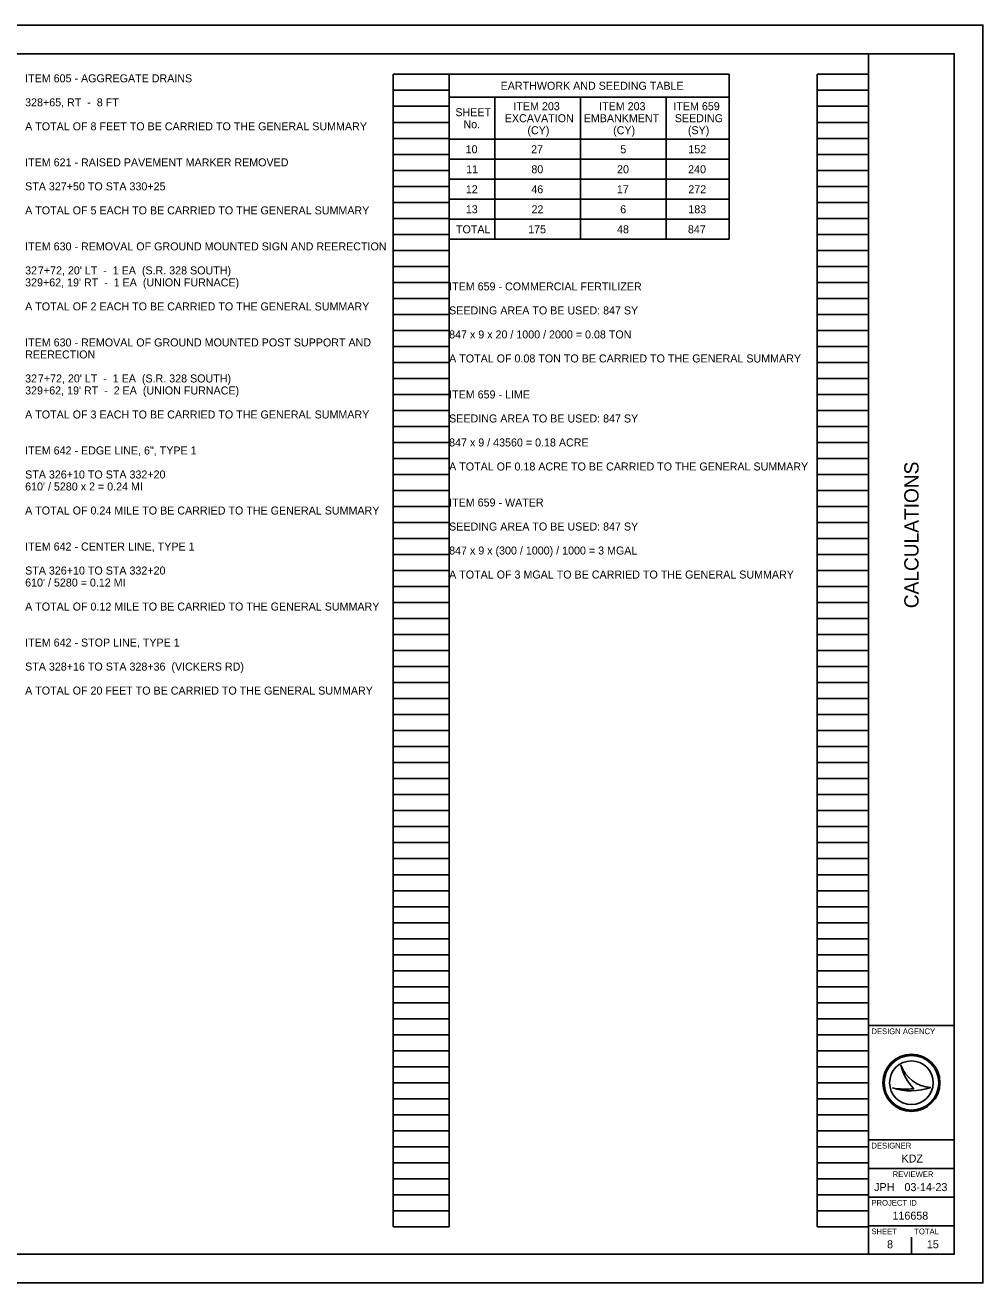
# Model space of a CAD drawing. Extents: x 0 to 34, y 0 to 22.
# Drawn here: x 17.24 to 34, y 0 to 22 of the extents above; entities that cross this region are included whole.
import ezdxf

# ---------------------------------------------------------------- set-up
doc = ezdxf.new("R2010")
doc.units = 0
for name, color, linetype in [('SH_Border', 7, 'Continuous'), ('SH_Cut_Line', 7, 'Continuous'), ('SH_Data', 7, 'Continuous'), ('SH_Text', 7, 'Continuous')]:
    doc.layers.add(name, color=color, linetype=linetype)

msp = doc.modelspace()

# ---------------------------------------------------------------- linework, layer by layer
at = {"layer": 'SH_Border'}
for p, q in [((32, 0.5), (32, 21.5)), ((32, 4.5), (33.5, 4.5)), ((32, 2.5), (33.5, 2.5)), ((32, 2), (33.5, 2)), ((32, 1.5), (33.5, 1.5)), ((32, 1), (33.5, 1))]:
    msp.add_line(p, q, dxfattribs=at)
msp.add_lwpolyline([(1.5, 21.5), (33.5, 21.5), (33.5, 0.5), (1.5, 0.5)], close=True, dxfattribs=at)
at = {"layer": 'SH_Cut_Line'}
msp.add_lwpolyline([(0, 0), (34, 0), (34, 22), (0, 22)], close=True, dxfattribs=at)
at = {"layer": 'SH_Data'}
for p, q in [((23.68, 0.98), (23.68, 21.14)), ((23.68, 21.14), (24.66, 21.14)), ((24.66, 0.98), (24.66, 21.14)), ((31.1, 0.98), (31.1, 21.14)), ((31.1, 21.14), (32, 21.14)), ((32, 0.98), (32, 21.14)), ((23.68, 20.86), (24.66, 20.86)), ((31.1, 20.86), (32, 20.86)), ((23.68, 20.58), (24.66, 20.58)), ((31.1, 20.58), (32, 20.58)), ((23.68, 20.3), (24.66, 20.3)), ((31.1, 20.3), (32, 20.3)), ((23.68, 20.02), (24.66, 20.02)), ((31.1, 20.02), (32, 20.02)), ((23.68, 19.74), (24.66, 19.74)), ((31.1, 19.74), (32, 19.74)), ((23.68, 19.46), (24.66, 19.46)), ((31.1, 19.46), (32, 19.46)), ((23.68, 19.18), (24.66, 19.18)), ((31.1, 19.18), (32, 19.18)), ((23.68, 18.9), (24.66, 18.9)), ((31.1, 18.9), (32, 18.9)), ((23.68, 18.62), (24.66, 18.62)), ((31.1, 18.62), (32, 18.62)), ((23.68, 18.34), (24.66, 18.34)), ((31.1, 18.34), (32, 18.34)), ((23.68, 18.06), (24.66, 18.06)), ((31.1, 18.06), (32, 18.06)), ((23.68, 17.78), (24.66, 17.78)), ((31.1, 17.78), (32, 17.78)), ((23.68, 17.5), (24.66, 17.5)), ((31.1, 17.5), (32, 17.5)), ((23.68, 17.22), (24.66, 17.22)), ((31.1, 17.22), (32, 17.22)), ((23.68, 16.94), (24.66, 16.94)), ((31.1, 16.94), (32, 16.94)), ((23.68, 16.66), (24.66, 16.66)), ((31.1, 16.66), (32, 16.66)), ((23.68, 16.38), (24.66, 16.38)), ((31.1, 16.38), (32, 16.38)), ((23.68, 16.1), (24.66, 16.1)), ((31.1, 16.1), (32, 16.1)), ((23.68, 15.82), (24.66, 15.82)), ((31.1, 15.82), (32, 15.82)), ((23.68, 15.54), (24.66, 15.54)), ((31.1, 15.54), (32, 15.54)), ((23.68, 15.26), (24.66, 15.26)), ((31.1, 15.26), (32, 15.26)), ((23.68, 14.98), (24.66, 14.98)), ((31.1, 14.98), (32, 14.98)), ((23.68, 14.7), (24.66, 14.7)), ((31.1, 14.7), (32, 14.7)), ((23.68, 14.42), (24.66, 14.42)), ((31.1, 14.42), (32, 14.42)), ((23.68, 14.14), (24.66, 14.14)), ((31.1, 14.14), (32, 14.14)), ((23.68, 13.86), (24.66, 13.86)), ((31.1, 13.86), (32, 13.86)), ((23.68, 13.58), (24.66, 13.58)), ((31.1, 13.58), (32, 13.58)), ((23.68, 13.3), (24.66, 13.3)), ((31.1, 13.3), (32, 13.3)), ((23.68, 13.02), (24.66, 13.02)), ((31.1, 13.02), (32, 13.02)), ((23.68, 12.74), (24.66, 12.74)), ((31.1, 12.74), (32, 12.74)), ((23.68, 12.46), (24.66, 12.46)), ((31.1, 12.46), (32, 12.46)), ((23.68, 12.18), (24.66, 12.18)), ((31.1, 12.18), (32, 12.18)), ((23.68, 11.9), (24.66, 11.9)), ((31.1, 11.9), (32, 11.9)), ((23.68, 11.62), (24.66, 11.62)), ((31.1, 11.62), (32, 11.62)), ((23.68, 11.34), (24.66, 11.34)), ((31.1, 11.34), (32, 11.34)), ((23.68, 11.06), (24.66, 11.06)), ((31.1, 11.06), (32, 11.06)), ((23.68, 10.78), (24.66, 10.78)), ((31.1, 10.78), (32, 10.78)), ((23.68, 10.5), (24.66, 10.5)), ((31.1, 10.5), (32, 10.5)), ((23.68, 10.22), (24.66, 10.22)), ((31.1, 10.22), (32, 10.22)), ((23.68, 9.94), (24.66, 9.94)), ((31.1, 9.94), (32, 9.94)), ((23.68, 9.66), (24.66, 9.66)), ((31.1, 9.66), (32, 9.66)), ((23.68, 9.38), (24.66, 9.38)), ((31.1, 9.38), (32, 9.38)), ((23.68, 9.1), (24.66, 9.1)), ((31.1, 9.1), (32, 9.1)), ((23.68, 8.82), (24.66, 8.82)), ((31.1, 8.82), (32, 8.82)), ((23.68, 8.54), (24.66, 8.54)), ((31.1, 8.54), (32, 8.54)), ((23.68, 8.26), (24.66, 8.26)), ((31.1, 8.26), (32, 8.26)), ((23.68, 7.98), (24.66, 7.98)), ((31.1, 7.98), (32, 7.98)), ((23.68, 7.7), (24.66, 7.7)), ((31.1, 7.7), (32, 7.7)), ((23.68, 7.42), (24.66, 7.42)), ((31.1, 7.42), (32, 7.42)), ((23.68, 7.14), (24.66, 7.14)), ((31.1, 7.14), (32, 7.14)), ((23.68, 6.86), (24.66, 6.86)), ((31.1, 6.86), (32, 6.86)), ((23.68, 6.58), (24.66, 6.58)), ((31.1, 6.58), (32, 6.58)), ((23.68, 6.3), (24.66, 6.3)), ((31.1, 6.3), (32, 6.3)), ((23.68, 6.02), (24.66, 6.02)), ((31.1, 6.02), (32, 6.02)), ((23.68, 5.74), (24.66, 5.74)), ((31.1, 5.74), (32, 5.74)), ((23.68, 5.46), (24.66, 5.46)), ((31.1, 5.46), (32, 5.46)), ((23.68, 5.18), (24.66, 5.18)), ((31.1, 5.18), (32, 5.18)), ((23.68, 4.9), (24.66, 4.9)), ((31.1, 4.9), (32, 4.9)), ((23.68, 4.62), (24.66, 4.62)), ((31.1, 4.62), (32, 4.62)), ((23.68, 4.34), (24.66, 4.34)), ((31.1, 4.34), (32, 4.34)), ((23.68, 4.06), (24.66, 4.06)), ((31.1, 4.06), (32, 4.06)), ((23.68, 3.78), (24.66, 3.78)), ((31.1, 3.78), (32, 3.78)), ((32.567, 3.81), (32.567, 3.81)), ((23.68, 3.5), (24.66, 3.5)), ((31.1, 3.5), (32, 3.5)), ((32.417, 3.41), (32.417, 3.41)), ((32.75, 3.5), (32.75, 3.5)), ((33.087, 3.419), (33.087, 3.419)), ((23.68, 3.22), (24.66, 3.22)), ((31.1, 3.22), (32, 3.22)), ((23.68, 2.94), (24.66, 2.94)), ((31.1, 2.94), (32, 2.94)), ((23.68, 2.66), (24.66, 2.66)), ((31.1, 2.66), (32, 2.66)), ((23.68, 2.38), (24.66, 2.38)), ((31.1, 2.38), (32, 2.38)), ((23.68, 2.1), (24.66, 2.1)), ((31.1, 2.1), (32, 2.1)), ((23.68, 1.82), (24.66, 1.82)), ((31.1, 1.82), (32, 1.82)), ((23.68, 1.54), (24.66, 1.54)), ((31.1, 1.54), (32, 1.54)), ((23.68, 1.26), (24.66, 1.26)), ((31.1, 1.26), (32, 1.26)), ((23.68, 0.98), (24.66, 0.98)), ((31.1, 0.98), (32, 0.98)), ((32.375, 0.675), (32.375, 0.675)), ((32.75, 0.5), (32.75, 0.8))]:
    msp.add_line(p, q, dxfattribs=at)
for radius in [0.5, 0.477, 0.477, 0.382]:
    msp.add_circle((32.75, 3.5), radius, dxfattribs=at)
for centre, radius, start, end in [((33.116, 3.998), 0.58, 198.9257, 198.9319), ((33.347, 3.97), 0.796, 191.6379, 191.6421), ((33.116, 3.998), 0.58, 198.9319, 267.1657), ((33.347, 3.97), 0.796, 191.6421, 226.0947), ((32.739, 4.37), 1.013, 251.4576, 290.0832), ((32.648, 4.654), 1.266, 259.4964, 259.4995), ((32.739, 4.37), 1.013, 251.4527, 251.4576), ((32.648, 4.654), 1.266, 259.4995, 276.6672)]:
    msp.add_arc(centre, radius, start, end, dxfattribs=at)
at = {"layer": 'SH_Text'}
for p, q in [((29.56, 21.14), (24.66, 21.14)), ((24.66, 21.14), (24.66, 18.254)), ((29.56, 21.14), (29.56, 18.254)), ((29.56, 20.74), (24.66, 20.74)), ((25.46, 20.74), (25.46, 18.254)), ((26.96, 20.74), (26.96, 18.254)), ((28.46, 20.74), (28.46, 18.254)), ((29.56, 20.004), (24.66, 20.004)), ((29.56, 19.654), (24.66, 19.654)), ((29.56, 19.304), (24.66, 19.304)), ((29.56, 18.954), (24.66, 18.954)), ((29.56, 18.604), (24.66, 18.604)), ((29.56, 18.254), (24.66, 18.254))]:
    msp.add_line(p, q, dxfattribs=at)

# ---------------------------------------------------------------- texts
at = {"layer": 'SH_Data'}
msp.add_text('CALCULATIONS', height=0.25, rotation=90, dxfattribs=at).set_placement((32.875, 11.801))
for s, height, p in [('DESIGN AGENCY', 0.1, (32.05, 4.35)), ('DESIGNER', 0.1, (32.05, 2.35)), ('KDZ', 0.14, (32.577, 2.105)), ('REVIEWER', 0.1, (32.422, 1.85)), ('JPH', 0.14, (32.098, 1.605)), ('03-14-23', 0.14, (32.629, 1.605)), ('PROJECT ID', 0.1, (32.05, 1.35)), ('116658', 0.14, (32.419, 1.105)), ('SHEET', 0.1, (32.05, 0.85)), ('TOTAL', 0.1, (32.8, 0.85)), ('8', 0.14, (32.324, 0.605)), ('15', 0.14, (33.02, 0.605))]:
    msp.add_text(s, height=height, dxfattribs=at).set_placement(p)
at = {"layer": 'SH_Text'}
for s, p in [('ITEM 605 - AGGREGATE DRAINS', (17.24, 21)), ('EARTHWORK AND SEEDING TABLE', (25.561, 20.87)), ('328+65, RT  -  8 FT', (17.24, 20.58)), ('SHEET', (24.769, 20.407)), ('ITEM 203', (25.785, 20.512)), ('ITEM 203', (27.285, 20.512)), ('ITEM 659', (28.584, 20.512)), ('A TOTAL OF 8 FEET TO BE CARRIED TO THE GENERAL SUMMARY', (17.24, 20.16)), ('No.', (24.91, 20.197)), ('EXCAVATION', (25.634, 20.302)), ('EMBANKMENT', (27.015, 20.302)), ('SEEDING', (28.609, 20.302)), ('(CY)', (26.03, 20.092)), ('(CY)', (27.53, 20.092)), ('(SY)', (28.838, 20.092)), ('10', (24.949, 19.759)), ('27', (26.095, 19.759)), ('5', (27.656, 19.759)), ('152', (28.846, 19.759)), ('ITEM 621 - RAISED PAVEMENT MARKER REMOVED', (17.24, 19.53)), ('11', (24.958, 19.409)), ('80', (26.099, 19.409)), ('20', (27.599, 19.409)), ('240', (28.843, 19.409)), ('STA 327+50 TO STA 330+25', (17.24, 19.11)), ('12', (24.952, 19.059)), ('46', (26.098, 19.059)), ('17', (27.595, 19.059)), ('272', (28.846, 19.059)), ('A TOTAL OF 5 EACH TO BE CARRIED TO THE GENERAL SUMMARY', (17.24, 18.69)), ('13', (24.952, 18.709)), ('22', (26.102, 18.709)), ('6', (27.654, 18.709)), ('183', (28.846, 18.709)), ('TOTAL', (24.78, 18.359)), ('175', (26.043, 18.359)), ('48', (27.598, 18.359)), ('847', (28.839, 18.359)), ('ITEM 630 - REMOVAL OF GROUND MOUNTED SIGN AND REERECTION', (17.24, 18.06)), ('32', (17.24, 17.64)), ("7+72, 20' LT  -  1 EA  (S.R. 328 SOUTH)", (17.463, 17.64)), ("329+62, 19' RT  -  1 EA  (UNION FURNACE)", (17.24, 17.43)), ('ITEM 659 - COMMERCIAL FERTILIZER', (24.66, 17.36)), ('A TOTAL OF 2 EACH TO BE CARRIED TO THE GENERAL SUMMARY', (17.24, 17.01)), ('SEEDING AREA TO BE USED: 847 SY', (24.66, 16.94)), ('ITEM 630 - REMOVAL OF GROUND MOUNTED POST SUPPORT AND ', (17.24, 16.38)), ('847 x 9 x 20 / 1000 / 2000 = 0.08 TON', (24.66, 16.52)), ('REERECTION', (17.24, 16.17)), ('A TOTAL OF 0.08 TON TO BE CARRIED TO THE GENERAL SUMMARY', (24.66, 16.1)), ('32', (17.24, 15.75)), ("7+72, 20' LT  -  1 EA  (S.R. 328 SOUTH)", (17.463, 15.75)), ("329+62, 19' RT  -  2 EA  (UNION FURNACE)", (17.24, 15.54)), ('ITEM 659 - LIME', (24.66, 15.47)), ('A TOTAL OF 3 EACH TO BE CARRIED TO THE GENERAL SUMMARY', (17.24, 15.12)), ('SEEDING AREA TO BE USED: 847 SY', (24.66, 15.05)), ('847 x 9 / 43560 = 0.18 ACRE', (24.66, 14.63)), ('ITEM 642 - EDGE LINE, 6", TYPE 1', (17.24, 14.49)), ('A TOTAL OF 0.18 ACRE TO BE CARRIED TO THE GENERAL SUMMARY', (24.66, 14.21)), ('STA 326+10 TO STA 332+20', (17.24, 14.07)), ("610' / 5280 x 2 = 0.24 MI", (17.24, 13.86)), ('ITEM 659 - WATER', (24.66, 13.58)), ('A TOTAL OF 0.24 MILE TO BE CARRIED TO THE GENERAL SUMMARY', (17.24, 13.44)), ('SEEDING AREA TO BE USED: 847 SY', (24.66, 13.16)), ('ITEM 642 - CENTER LINE, TYPE 1', (17.24, 12.81)), ('847 x 9 x (300 / 1000) / 1000 = 3 MGAL', (24.66, 12.74)), ('STA 326+10 TO STA 332+20', (17.24, 12.39)), ("610' / 5280 = 0.12 MI", (17.24, 12.18)), ('A TOTAL OF 3 MGAL TO BE CARRIED TO THE GENERAL SUMMARY', (24.66, 12.32)), ('A TOTAL OF 0.12 MILE TO BE CARRIED TO THE GENERAL SUMMARY', (17.24, 11.76)), ('ITEM 642 - STOP LINE, TYPE 1', (17.24, 11.13)), ('STA 328+16 TO STA 328+36  (VICKERS RD)', (17.24, 10.71)), ('A TOTAL OF 20 FEET TO BE CARRIED TO THE GENERAL SUMMARY', (17.24, 10.29))]:
    msp.add_text(s, height=0.14, dxfattribs=at).set_placement(p)

doc.saveas('drawing.dxf')
